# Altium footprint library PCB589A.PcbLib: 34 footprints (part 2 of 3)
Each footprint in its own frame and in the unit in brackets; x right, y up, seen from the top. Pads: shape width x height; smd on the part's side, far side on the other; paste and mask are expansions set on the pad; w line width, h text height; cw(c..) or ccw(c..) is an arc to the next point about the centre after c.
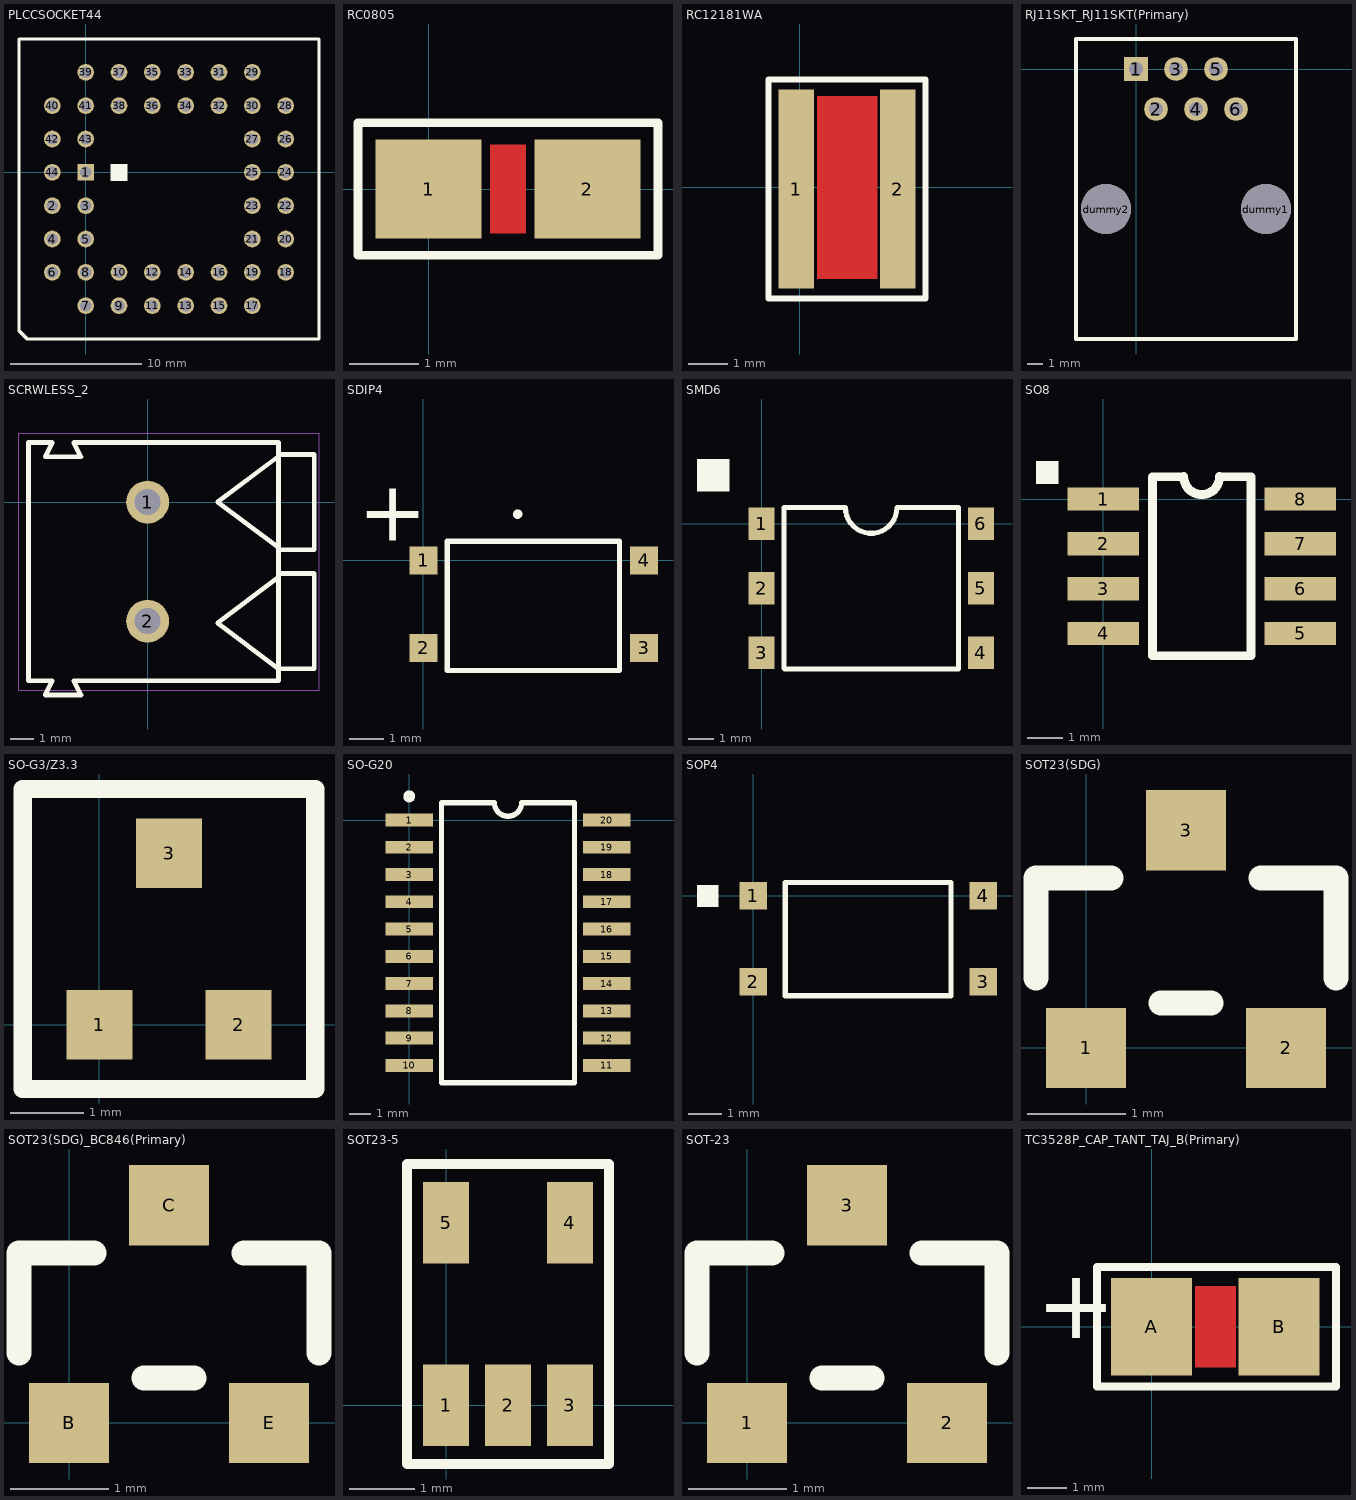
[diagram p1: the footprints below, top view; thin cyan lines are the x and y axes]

## PLCCSOCKET44 [mil]
pads (44):
  rect 50x50 hole 34: 1(0,0)
  round 50 hole 34: 2(-100,-100) 3(0,-100) 4(-100,-200) 5(0,-200) 6(-100,-300) 7(0,-400) 8(0,-300) 9(100,-400) 10(100,-300) 11(200,-400) 12(200,-300) 13(300,-400) 14(300,-300) 15(400,-400) 16(400,-300) 17(500,-400) 18(600,-300) 19(500,-300) 20(600,-200) 21(500,-200) 22(600,-100) 23(500,-100) 24(600,0) 25(500,0) 26(600,100) 27(500,100) 28(600,200) 29(500,300) 30(500,200) 31(400,300) 32(400,200) 33(300,300) 34(300,200) 35(200,300) 36(200,200) 37(100,300) 38(100,200) 39(0,300) 40(-100,200) 41(0,200) 42(-100,100) 43(0,100) 44(-100,0)
Top Overlay:
  region: 75,25 125,25 125,-25 75,-25
  lines w10: -200,-475 -175,-500 700,-500 700,400 -200,400 -200,-475

## RC0805 [mil]
pads (2):
  rect 60x56 smd: 1(0,0) 2(90,0)
Top Layer:
  region: 55,-25 55,25 35,25 35,-25
Top Overlay:
  lines w5: -40,-37.5 130,-37.5 130,37.5 -40,37.5 -40,-37.5

## RC12181WA [mm]
pads (2):
  rect 0.9x5 smd: 1(-0.08,-0.04) 2(2.47,-0.04)
Top Layer:
  region: 1.95,-2.3 1.95,2.3 0.45,2.3 0.45,-2.3
Top Overlay:
  lines w0.152: -0.78,-2.79 3.17,-2.79 3.17,2.71 -0.78,2.71 -0.78,-2.79

## RJ11SKT_RJ11SKT(Primary) [mm]
pads (8):
  rect 1.5x1.5 hole 0.9: 1(0,0)
  round 1.5 hole 0.9: 2(1.27,-2.54) 3(2.54,0) 4(3.81,-2.54) 5(5.08,0) 6(6.35,-2.54)
  round 3.175 hole 3.175: dummy1(8.255,-8.89) dummy2(-1.905,-8.89)
Top Overlay:
  lines w0.254: -3.81,-17.145 6.35,-17.145 10.16,-17.145 10.16,1.27 10.16,1.905 -3.81,1.905 -3.81,-10.795 -3.81,-13.335 -3.81,-17.145

## SCRWLESS_2 [mm]
pads (2):
  round 1.8 hole 1.1: 1(0,0) 2(0,-5)
Top Overlay:
  lines w0.2: 5.485,-6.985 2.945,-5.08 5.485,-3.175 ; 5.485,1.905 2.945,0 5.5,-1.9 ; 5.5,-7 7,-7 7,-3 5.5,-3 ; 5.5,-2 7,-2 7,2 5.5,2 ; -5,-7.5 -4,-7.5 -4.3,-8.1 -2.8,-8.1 -3.1,-7.5 5.5,-7.5 5.5,2.5 -3.1,2.5 -2.8,1.9 -4.3,1.9 -4,2.5 -5,2.5 -5,-7.5
Mechanical 1:
  lines w0.025: -5.4,-7.9 -5.4,2.9 7.2,2.9 7.2,-7.9 -5.4,-7.9

## SDIP4 [mil]
pads (4):
  rect 32x32 smd: 1(0.39,0) 2(0.39,-100) 3(252.36,-100) 4(252.36,0)
Top Overlay:
  circle w10: c107.87,52.76 r0.39
  lines w5.98: 27.56,-125.98 224.41,-125.98 224.41,21.65 27.56,21.65 27.56,-125.98
  text "+" at -74.61,-0.59 h118.11

## SMD6 [mil]
pads (6):
  rect 40x50 smd: 1(0,0) 2(0,-100) 3(0,-200) 4(340,-200) 5(340,-100) 6(340,0)
Top Overlay:
  region: -100,50 -50,50 -50,100 -100,100
  lines w7.87: 35,-224.41 35,25 130,25 ccw(c170,25) 210,25 305,25 305,-225 ; 35.59,-225 305,-225 ; 304.41,-224.41 305,-225

## SO8 [mil]
pads (8):
  rect 80x26 smd: 1(0,0) 2(0,-50) 3(0,-100) 4(0,-150) 5(220,-150) 6(220,-100) 7(220,-50) 8(220,0)
Top Overlay:
  region: -75,42.13 -50,42.13 -50,17.13 -75,17.13
  lines w9.84: 90,25 55,25 55,-175 165,-175 165,25 130,25
  lines w10: 90,25 ccw(c110,25) 130,25

## SO-G3/Z3.3 [mm]
pads (3):
  rect 0.9x0.95 smd: 1(0,0) 2(1.9,0) 3(0.95,2.35)
Top Overlay:
  lines w0.25: -1.05,-0.875 -1.05,3.225 2.95,3.225 2.95,-0.875 -1.05,-0.875

## SO-G20 [mm]
pads (20):
  rect 2.2x0.6 smd: 1(0,0) 2(0,-1.27) 3(0,-2.54) 4(0,-3.81) 5(0,-5.08) 6(0,-6.35) 7(0,-7.62) 8(0,-8.89) 9(0,-10.16) 10(0,-11.43) 11(9.2,-11.43) 12(9.2,-10.16) 13(9.2,-8.89) 14(9.2,-7.62) 15(9.2,-6.35) 16(9.2,-5.08) 17(9.2,-3.81) 18(9.2,-2.54) 19(9.2,-1.27) 20(9.2,0)
Top Overlay:
  circle w0.25: c0,1.1 r0.15
  lines w0.25: 1.5,-12.24 1.5,0.81 3.965,0.81 ccw(c4.6,0.81) 5.235,0.81 7.7,0.81 7.7,-12.24 1.5,-12.24

## SOP4 [mil]
pads (4):
  rect 32x32 smd: 1(0,0) 2(0,-100) 3(267.72,-100) 4(267.72,0)
Top Overlay:
  region: -65.16,12.6 -40.16,12.6 -40.16,-12.4 -65.16,-12.4
  lines w5.98: 37.4,-116.14 230.31,-116.14 230.31,15.75 37.4,15.75 37.4,-116.14

## SOT23(SDG) [mil]
pads (3):
  rect 32x32 smd: 1(0,0) 2(80,0) 3(40,87)
Top Overlay:
  lines w10: -20,28 -20,68 10,68 ; 30,18 50,18 ; 70,68 100,68 100,28

## SOT23(SDG)_BC846(Primary) [mil]
pads (3):
  rect 32x32 smd: B(0,0) C(40,87) E(80,0)
Top Overlay:
  lines w10: -20,28 -20,68 10,68 ; 30,18 50,18 ; 70,68 100,68 100,28

## SOT23-5 [mm]
pads (5):
  rect 0.7x1.25 smd: 1(0,0) 2(0.95,0) 3(1.9,0) 4(1.9,2.8) 5(0,2.8)
Top Overlay:
  lines w0.15: -0.6,-0.9 -0.6,3.7 2.5,3.7 2.5,-0.9 -0.6,-0.9

## SOT-23 [mil]
pads (3):
  rect 32x32 smd: 1(0,0) 2(80,0) 3(40,87)
Top Overlay:
  lines w10: -20,28 -20,68 10,68 ; 30,18 50,18 ; 70,68 100,68 100,28

## TC3528P_CAP_TANT_TAJ_B(Primary) [mil]
pads (2):
  rect 80x96 smd: A(0,0) B(126,0)
Top Layer:
  region: 83,-40 83,40 43,40 43,-40
Top Overlay:
  lines w7.87: -53.94,-59.06 182.28,-59.06 182.28,59.06 -53.94,59.06 -53.94,-59.06
  text "+" at -114.17,-33.86 h118.11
